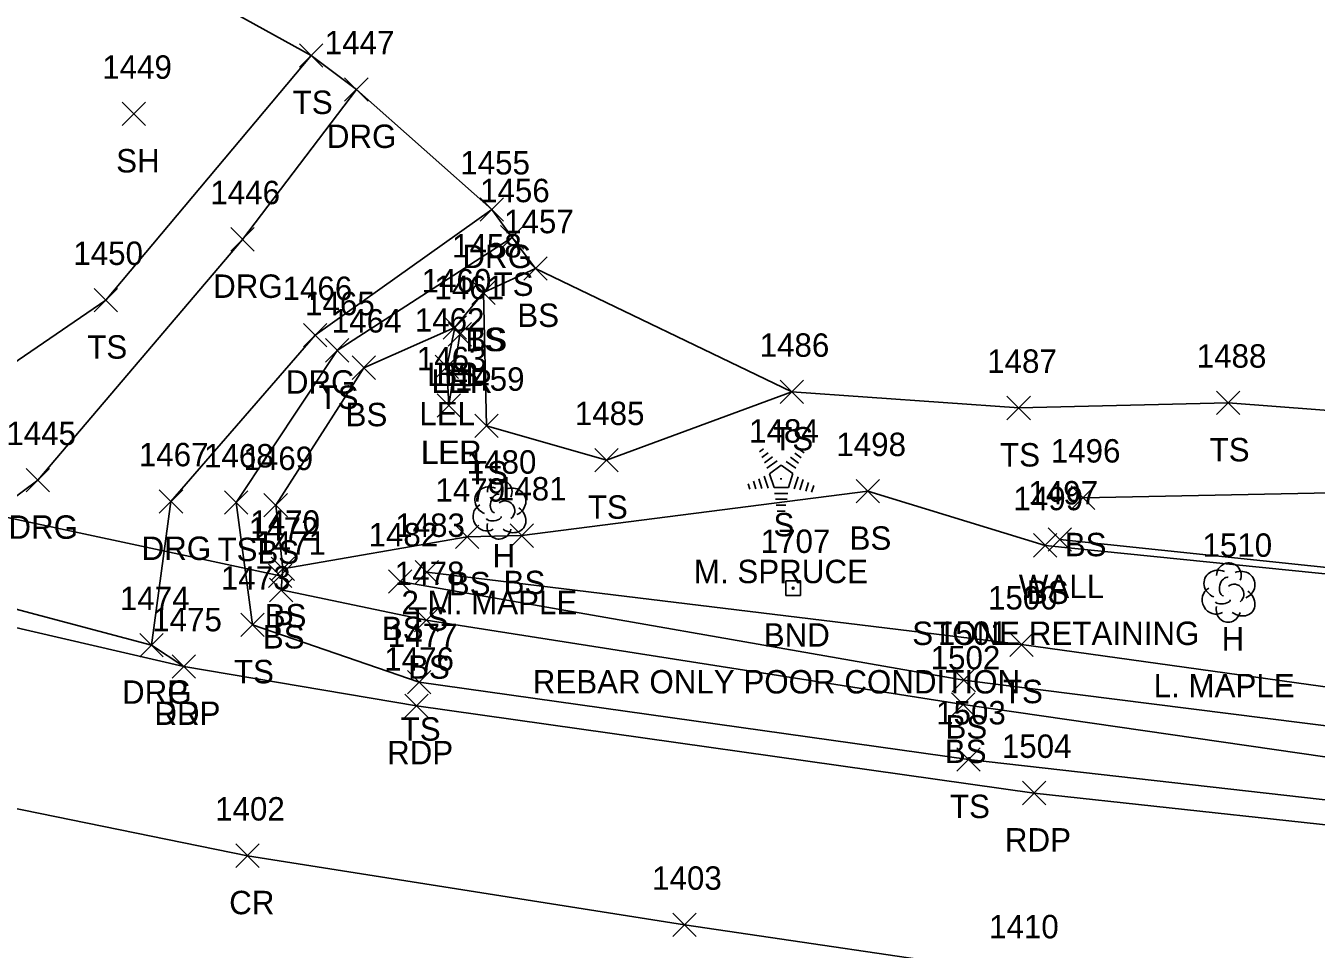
# Model space of a CAD drawing. Extents: x 1547013 to 1549434, y 267998 to 268739.
# Drawn here: x 1548667.4 to 1548777.6, y 268079 to 268157.8 of the extents above; entities that cross this region are included whole.
import ezdxf

# ---------------------------------------------------------------- set-up
doc = ezdxf.new("R2010")
doc.units = 0
for name, color, linetype in [('D_A', 7, 'Continuous'), ('D_I', 7, 'Continuous'), ('D_TIC', 7, 'Continuous'), ('DCP', 7, 'Continuous'), ('L_A', 7, 'Continuous'), ('L_C', 7, 'Continuous'), ('L_I', 7, 'Continuous'), ('L_TIC', 7, 'Continuous'), ('LARO', 7, 'Continuous'), ('LELB', 7, 'Continuous'), ('LSOGP', 7, 'Continuous'), ('LTC', 7, 'Continuous'), ('LTD', 7, 'Continuous'), ('LW', 7, 'Continuous'), ('M_A', 7, 'Continuous'), ('M_C', 7, 'Continuous'), ('M_I', 7, 'Continuous'), ('MHBP', 7, 'Continuous'), ('P_A', 7, 'Continuous'), ('P_I', 7, 'Continuous'), ('P_TIC', 7, 'Continuous'), ('PET', 7, 'Continuous'), ('PRC', 7, 'Continuous'), ('R_A', 7, 'Continuous'), ('R_I', 7, 'Continuous'), ('R_TIC', 7, 'Continuous'), ('RDG', 7, 'Continuous'), ('RDP', 7, 'Continuous')]:
    doc.layers.add(name, color=color, linetype=linetype)

msp = doc.modelspace()

# ---------------------------------------------------------------- linework, layer by layer
at = {"layer": 'D_TIC'}
for points in [[(1548688.17, 268109.86), (1548690.17, 268111.86)], [(1548690.17, 268109.86), (1548688.17, 268111.86)]]:
    msp.add_lwpolyline(points, dxfattribs=at)
at = {"layer": 'DCP'}
msp.add_lwpolyline([(1548636.86, 268122.04), (1548689.17, 268110.86)], dxfattribs=at)
at = {"layer": 'L_TIC'}
for points in [[(1548690.82, 268154.29), (1548692.82, 268156.29)], [(1548692.82, 268154.29), (1548690.82, 268156.29)], [(1548675.67, 268149.3), (1548677.67, 268151.3)], [(1548677.67, 268149.3), (1548675.67, 268151.3)], [(1548707.97, 268138.76), (1548709.97, 268140.76)], [(1548709.97, 268138.76), (1548707.97, 268140.76)], [(1548709.97, 268136.11), (1548711.97, 268138.11)], [(1548711.97, 268136.11), (1548709.97, 268138.11)], [(1548673.28, 268133.4), (1548675.28, 268135.4)], [(1548675.28, 268133.4), (1548673.28, 268135.4)], [(1548705.53, 268134.04), (1548707.53, 268136.04)], [(1548707.53, 268134.04), (1548705.53, 268136.04)], [(1548705.53, 268134.04), (1548707.53, 268136.04)], [(1548707.53, 268134.04), (1548705.53, 268136.04)], [(1548703.07, 268131.06), (1548705.07, 268133.06)], [(1548705.07, 268131.06), (1548703.07, 268133.06)], [(1548703.07, 268131.06), (1548705.07, 268133.06)], [(1548705.07, 268131.06), (1548703.07, 268133.06)], [(1548703.51, 268130.48), (1548705.51, 268132.48)], [(1548705.51, 268130.48), (1548703.51, 268132.48)], [(1548693.03, 268129.11), (1548695.03, 268131.11)], [(1548695.03, 268129.11), (1548693.03, 268131.11)], [(1548702.4, 268127.71), (1548704.4, 268129.71)], [(1548704.4, 268127.71), (1548702.4, 268129.71)], [(1548695.31, 268127.63), (1548697.31, 268129.63)], [(1548697.31, 268127.63), (1548695.31, 268129.63)], [(1548731.85, 268125.56), (1548733.85, 268127.56)], [(1548733.85, 268125.56), (1548731.85, 268127.56)], [(1548702.57, 268124.41), (1548704.57, 268126.41)], [(1548704.57, 268124.41), (1548702.57, 268126.41)], [(1548702.57, 268124.41), (1548704.57, 268126.41)], [(1548704.57, 268124.41), (1548702.57, 268126.41)], [(1548769.11, 268124.63), (1548771.11, 268126.63)], [(1548771.11, 268124.63), (1548769.11, 268126.63)], [(1548751.22, 268124.19), (1548753.22, 268126.19)], [(1548753.22, 268124.19), (1548751.22, 268126.19)], [(1548705.78, 268122.66), (1548707.78, 268124.66)], [(1548707.78, 268122.66), (1548705.78, 268124.66)], [(1548716.02, 268119.73), (1548718.02, 268121.73)], [(1548718.02, 268119.73), (1548716.02, 268121.73)], [(1548738.34, 268117.08), (1548740.34, 268119.08)], [(1548740.34, 268117.08), (1548738.34, 268119.08)], [(1548684.4, 268116.11), (1548686.4, 268118.11)], [(1548686.4, 268116.11), (1548684.4, 268118.11)], [(1548687.78, 268115.89), (1548689.78, 268117.89)], [(1548689.78, 268115.89), (1548687.78, 268117.89)], [(1548756.71, 268116.53), (1548758.71, 268118.53)], [(1548758.71, 268116.53), (1548756.71, 268118.53)], [(1548704.12, 268113.19), (1548706.12, 268115.19)], [(1548706.12, 268113.19), (1548704.12, 268115.19)], [(1548708.8, 268113.29), (1548710.8, 268115.29)], [(1548710.8, 268113.29), (1548708.8, 268115.29)], [(1548708.8, 268113.29), (1548710.8, 268115.29)], [(1548710.8, 268113.29), (1548708.8, 268115.29)], [(1548753.48, 268112.46), (1548755.48, 268114.46)], [(1548755.48, 268112.46), (1548753.48, 268114.46)], [(1548754.74, 268112.95), (1548756.74, 268114.95)], [(1548756.74, 268112.95), (1548754.74, 268114.95)], [(1548688.4, 268110.45), (1548690.4, 268112.45)], [(1548690.4, 268110.45), (1548688.4, 268112.45)], [(1548688.4, 268110.45), (1548690.4, 268112.45)], [(1548690.4, 268110.45), (1548688.4, 268112.45)], [(1548700.68, 268110.18), (1548702.68, 268112.18)], [(1548702.68, 268110.18), (1548700.68, 268112.18)], [(1548698.4, 268109.37), (1548700.4, 268111.37)], [(1548700.4, 268109.37), (1548698.4, 268111.37)], [(1548688.24, 268108.65), (1548690.24, 268110.65)], [(1548690.24, 268108.65), (1548688.24, 268110.65)], [(1548685.8, 268105.68), (1548687.8, 268107.68)], [(1548687.8, 268105.68), (1548685.8, 268107.68)], [(1548700.64, 268106.07), (1548702.64, 268108.07)], [(1548702.64, 268106.07), (1548700.64, 268108.07)], [(1548751.46, 268103.98), (1548753.46, 268105.98)], [(1548753.46, 268103.98), (1548751.46, 268105.98)], [(1548751.46, 268103.98), (1548753.46, 268105.98)], [(1548753.46, 268103.98), (1548751.46, 268105.98)], [(1548700.04, 268100.78), (1548702.04, 268102.78)], [(1548702.04, 268100.78), (1548700.04, 268102.78)], [(1548746.53, 268100.96), (1548748.53, 268102.96)], [(1548748.53, 268100.96), (1548746.53, 268102.96)], [(1548746.47, 268098.87), (1548748.47, 268100.87)], [(1548748.47, 268098.87), (1548746.47, 268100.87)], [(1548746.94, 268094.17), (1548748.94, 268096.17)], [(1548748.94, 268094.17), (1548746.94, 268096.17)]]:
    msp.add_lwpolyline(points, dxfattribs=at)
at = {"layer": 'LARO'}
for points in [[(1548704.07, 268132.06), (1548703.4, 268128.71), (1548703.57, 268125.41)], [(1548704.51, 268131.48), (1548703.57, 268125.41)]]:
    msp.add_lwpolyline(points, dxfattribs=at)
at = {"layer": 'LELB'}
for points in [[(1548691.82, 268155.29), (1548674.28, 268134.4), (1548659.83, 268124.52), (1548649.05, 268118.48), (1548639.38, 268118.89)], [(1548708.97, 268139.76), (1548694.03, 268130.11), (1548685.4, 268117.11), (1548686.8, 268106.68), (1548701.04, 268101.78), (1548747.94, 268095.17), (1548793.98, 268089.97), (1548842.52, 268087.31), (1548868.94, 268086.32)], [(1548710.97, 268137.11), (1548706.53, 268135.04), (1548704.07, 268132.06), (1548696.31, 268128.63), (1548688.78, 268116.89), (1548689.4, 268111.45), (1548689.24, 268109.65), (1548701.64, 268107.07), (1548747.47, 268099.87), (1548796.06, 268092.83), (1548842.33, 268090.57), (1548868.8, 268090.49)], [(1548706.53, 268135.04), (1548706.78, 268123.66), (1548717.02, 268120.73), (1548732.85, 268126.56), (1548752.22, 268125.19), (1548770.11, 268125.63), (1548809.24, 268122.64), (1548831.85, 268121.11), (1548870.82, 268123.01)], [(1548709.8, 268114.29), (1548739.34, 268118.08), (1548754.48, 268113.46), (1548791.6, 268109.68), (1548794.4, 268109.32), (1548819.52, 268109.84), (1548864.97, 268108.07), (1548873.06, 268107.6)], [(1548866.65, 268118.14), (1548838.78, 268114.29), (1548806.27, 268118), (1548784.51, 268118.06), (1548757.71, 268117.53)], [(1548689.4, 268111.45), (1548705.12, 268114.19), (1548709.8, 268114.29)], [(1548701.68, 268111.18), (1548752.46, 268104.98)], [(1548699.4, 268110.37), (1548747.53, 268101.96), (1548796.07, 268095.83), (1548842.07, 268093.87), (1548869.05, 268093.06)], [(1548752.46, 268104.98), (1548796.76, 268098.83), (1548842.79, 268096.87), (1548869.42, 268094.95)]]:
    msp.add_lwpolyline(points, dxfattribs=at)
at = {"layer": 'LSOGP'}
msp.add_lwpolyline([(1548809.24, 268122.64), (1548770.11, 268125.63), (1548752.22, 268125.19), (1548732.85, 268126.56), (1548710.97, 268137.11), (1548708.97, 268139.76), (1548707.23, 268142.13), (1548695.67, 268152.39), (1548691.82, 268155.29), (1548664.24, 268170.51)], dxfattribs=at)
at = {"layer": 'LTC'}
for p, q in [((1548730.09, 268121.44), (1548730.44, 268121.69)), ((1548730.3, 268120.97), (1548730.83, 268121.36)), ((1548730.51, 268120.51), (1548731.21, 268121.02)), ((1548732.74, 268120.98), (1548733.42, 268120.49)), ((1548733.12, 268121.33), (1548733.66, 268120.93)), ((1548733.49, 268121.68), (1548733.91, 268121.37)), ((1548730.72, 268120.04), (1548731.6, 268120.68)), ((1548730.94, 268119.58), (1548731.95, 268120.32)), ((1548731.95, 268120.32), (1548732.95, 268119.59)), ((1548732.37, 268120.63), (1548733.18, 268120.04)), ((1548729.12, 268118.72), (1548729.27, 268118.25)), ((1548729.58, 268118.93), (1548729.79, 268118.28)), ((1548730.03, 268119.15), (1548730.3, 268118.31)), ((1548730.49, 268119.37), (1548730.82, 268118.35)), ((1548730.94, 268119.58), (1548731.33, 268118.39)), ((1548732.95, 268119.59), (1548732.56, 268118.39)), ((1548733.39, 268119.32), (1548733.05, 268118.28)), ((1548733.83, 268119.07), (1548733.54, 268118.19)), ((1548734.28, 268118.82), (1548734.04, 268118.09)), ((1548732.56, 268118.39), (1548731.33, 268118.39)), ((1548732.52, 268117.89), (1548731.38, 268117.89)), ((1548734.72, 268118.57), (1548734.53, 268118)), ((1548732.44, 268117.39), (1548731.45, 268117.39)), ((1548732.35, 268116.89), (1548731.52, 268116.89)), ((1548732.27, 268116.39), (1548731.59, 268116.39))]:
    msp.add_line(p, q, dxfattribs=at)
at = {"layer": 'LTD'}
for p, q in [((1548707.87, 268116.58), (1548707.87, 268116.58)), ((1548707.87, 268116.58), (1548707.87, 268116.58)), ((1548770.12, 268109.48), (1548770.12, 268109.48)), ((1548770.12, 268109.48), (1548770.12, 268109.48))]:
    msp.add_line(p, q, dxfattribs=at)
for centre in [(1548707.91, 268118.02), (1548770.17, 268110.91)]:
    msp.add_arc(centre, 1.05, 335.5272, 180.9563, dxfattribs=at)
for centre, major_axis, ratio, start_param, end_param in [((1548707.08, 268117.25), (1.21, -0.51), 0.895232, 1.570796, 4.712389), ((1548707.66, 268117.04), (-0.208, -0.792), 0.645439, 3.141593, 6.283185), ((1548708.91, 268117.17), (-1.14, -0.48), 0.949671, 1.570796, 4.712389), ((1548706.78, 268115.87), (0.58, -1.04), 0.959034, 3.141593, 6.283185), ((1548708.37, 268116.42), (-0.5, 0.667), 0.989748, 3.141593, 6.283185), ((1548708.87, 268115.75), (-1.09, 0.79), 0.841452, 1.570796, 4.712389), ((1548707.41, 268115.83), (-0.625, -0.083), 0.423636, 0, 3.141593), ((1548707.87, 268115.08), (0.26, 1.06), 0.942809, 1.570796, 4.712389), ((1548769.33, 268110.14), (1.21, -0.51), 0.895232, 1.570796, 4.712389), ((1548771.16, 268110.06), (-1.14, -0.48), 0.949671, 1.570796, 4.712389), ((1548769.91, 268109.93), (-0.208, -0.792), 0.645439, 3.141593, 6.283185), ((1548770.62, 268109.31), (-0.5, 0.667), 0.989748, 3.141593, 6.283185), ((1548769.04, 268108.77), (0.58, -1.04), 0.959034, 3.141593, 6.283185), ((1548769.66, 268108.73), (-0.625, -0.083), 0.423636, 0, 3.141593), ((1548771.12, 268108.64), (-1.09, 0.79), 0.841452, 1.570796, 4.712389), ((1548770.12, 268107.98), (0.26, 1.06), 0.942809, 1.570796, 4.712389)]:
    msp.add_ellipse(centre, major_axis=major_axis, ratio=ratio, start_param=start_param, end_param=end_param, dxfattribs=at)
at = {"layer": 'LW'}
msp.add_lwpolyline([(1548755.74, 268113.95), (1548794.53, 268109.88), (1548819.57, 268110.3), (1548865.06, 268109.14)], dxfattribs=at)
at = {"layer": 'MHBP'}
msp.add_lwpolyline([(1548732.34, 268110.44), (1548733.59, 268110.44), (1548733.59, 268109.19), (1548732.34, 268109.19)], close=True, dxfattribs=at)
msp.add_circle((1548732.96, 268109.81), 0.0833, dxfattribs=at)
at = {"layer": 'P_TIC'}
for points in [[(1548679.93, 268102.12), (1548681.93, 268104.12)], [(1548681.93, 268102.12), (1548679.93, 268104.12)], [(1548699.8, 268098.76), (1548701.8, 268100.76)], [(1548701.8, 268098.76), (1548699.8, 268100.76)], [(1548752.55, 268091.31), (1548754.55, 268093.31)], [(1548754.55, 268091.31), (1548752.55, 268093.31)], [(1548685.38, 268085.96), (1548687.38, 268087.96)], [(1548687.38, 268085.96), (1548685.38, 268087.96)], [(1548722.69, 268080.05), (1548724.69, 268082.05)], [(1548724.69, 268080.05), (1548722.69, 268082.05)]]:
    msp.add_lwpolyline(points, dxfattribs=at)
at = {"layer": 'PET'}
msp.add_lwpolyline([(1548291.29, 268251.79), (1548331.75, 268232.06), (1548365.57, 268215.99), (1548397.04, 268199.92), (1548430.53, 268185.01), (1548469.56, 268167.88), (1548505.57, 268153.53), (1548548.45, 268139.73), (1548572.84, 268130.65), (1548596.65, 268123.57), (1548616.57, 268118.19), (1548655.34, 268109.04), (1548680.93, 268103.12), (1548700.8, 268099.76), (1548753.55, 268092.31), (1548788.11, 268088.53), (1548842.08, 268084.26), (1548868.98, 268083.24)], dxfattribs=at)
at = {"layer": 'PRC'}
msp.add_lwpolyline([(1548285.23, 268237.15), (1548330.43, 268214.75), (1548376.37, 268192.58), (1548426.54, 268169.59), (1548464.29, 268153.5), (1548497.35, 268140.09), (1548534.69, 268126.49), (1548572.93, 268114.69), (1548608.02, 268104.77), (1548637.81, 268097.38), (1548663.07, 268091.69), (1548686.38, 268086.96), (1548723.69, 268081.05), (1548751.9, 268076.9), (1548786.74, 268073.36), (1548818.76, 268070.54), (1548866.8, 268068.08)], dxfattribs=at)
at = {"layer": 'R_TIC'}
for points in [[(1548694.67, 268151.39), (1548696.67, 268153.39)], [(1548696.67, 268151.39), (1548694.67, 268153.39)], [(1548706.23, 268141.13), (1548708.23, 268143.13)], [(1548708.23, 268141.13), (1548706.23, 268143.13)], [(1548684.95, 268138.59), (1548686.95, 268140.59)], [(1548686.95, 268138.59), (1548684.95, 268140.59)], [(1548691.16, 268130.41), (1548693.16, 268132.41)], [(1548693.16, 268130.41), (1548691.16, 268132.41)], [(1548667.48, 268118.02), (1548669.48, 268120.02)], [(1548669.48, 268118.02), (1548667.48, 268120.02)], [(1548678.84, 268116.21), (1548680.84, 268118.21)], [(1548680.84, 268116.21), (1548678.84, 268118.21)], [(1548677.17, 268103.93), (1548679.17, 268105.93)], [(1548679.17, 268103.93), (1548677.17, 268105.93)], [(1548677.17, 268103.93), (1548679.17, 268105.93)], [(1548679.17, 268103.93), (1548677.17, 268105.93)], [(1548679.93, 268102.12), (1548681.93, 268104.12)], [(1548681.93, 268102.12), (1548679.93, 268104.12)]]:
    msp.add_lwpolyline(points, dxfattribs=at)
at = {"layer": 'RDG'}
for points in [[(1548657.06, 268110.53), (1548668.48, 268119.02), (1548685.95, 268139.59), (1548695.67, 268152.39)], [(1548707.23, 268142.13), (1548692.16, 268131.41), (1548679.84, 268117.21), (1548678.17, 268104.93)]]:
    msp.add_lwpolyline(points, dxfattribs=at)
at = {"layer": 'RDP'}
msp.add_lwpolyline([(1548655.34, 268109.04), (1548657.06, 268110.53), (1548678.17, 268104.93), (1548680.93, 268103.12)], dxfattribs=at)

# ---------------------------------------------------------------- texts
at = {"layer": 'D_A'}
msp.add_text('P', height=2, dxfattribs=at).set_placement((1548688.55, 268105.86))
at = {"layer": 'D_I'}
msp.add_text('1472', height=2, dxfattribs=at).set_placement((1548686.48, 268113.86))
at = {"layer": 'L_A'}
for s, p in [('TS', (1548690.23, 268150.29)), ('SH', (1548675.16, 268145.3)), ('TS', (1548707.38, 268134.76)), ('BS', (1548709.41, 268132.11)), ('TS', (1548704.94, 268130.04)), ('BS', (1548704.97, 268130.04)), ('TS', (1548672.69, 268129.4)), ('LEL', (1548701.71, 268127.06)), ('BS', (1548702.51, 268127.06)), ('LER', (1548702.09, 268126.48)), ('TS', (1548692.44, 268125.11)), ('BS', (1548694.75, 268123.63)), ('LEL', (1548701.04, 268123.71)), ('TS', (1548731.26, 268121.56)), ('LER', (1548701.16, 268120.41)), ('LEL', (1548701.21, 268120.41)), ('TS', (1548750.63, 268120.19)), ('TS', (1548768.52, 268120.63)), ('TS', (1548705.19, 268118.66)), ('TS', (1548715.43, 268115.73)), ('S', (1548731.28, 268114.23)), ('BS', (1548737.78, 268113.08)), ('BS', (1548756.15, 268112.53)), ('TS', (1548683.81, 268112.11)), ('BS', (1548687.22, 268111.89)), ('H', (1548707.3, 268111.58)), ('BS', (1548703.56, 268109.19)), ('BS', (1548708.24, 268109.29)), ('BS', (1548708.24, 268109.29)), ('WALL', (1548752.23, 268108.95)), ('BS', (1548752.92, 268108.46)), ('BS', (1548687.84, 268106.45)), ('BS', (1548687.84, 268106.45)), ('TS', (1548700.09, 268106.18)), ('BS', (1548687.68, 268104.65)), ('BS', (1548697.84, 268105.37)), ('H', (1548769.55, 268104.48)), ('TS', (1548685.21, 268101.68)), ('BS', (1548700.08, 268102.07)), ('TS', (1548750.87, 268099.98)), ('TS', (1548750.87, 268099.98)), ('BS', (1548745.97, 268096.96)), ('TS', (1548699.45, 268096.78)), ('BS', (1548745.91, 268094.87)), ('TS', (1548746.35, 268090.17))]:
    msp.add_text(s, height=2, dxfattribs=at).set_placement(p)
at = {"layer": 'L_C'}
for s, p in [('M. SPRUCE', (1548724.49, 268110.23)), ('2 M. MAPLE', (1548699.52, 268107.58)), ('STONE RETAINING', (1548743.13, 268104.95)), ('L. MAPLE', (1548763.74, 268100.48))]:
    msp.add_text(s, height=2, dxfattribs=at).set_placement(p)
at = {"layer": 'L_I'}
for s, p in [('1449', (1548673.97, 268153.3)), ('1456', (1548706.23, 268142.76)), ('1457', (1548708.28, 268140.11)), ('1458', (1548703.84, 268138.04)), ('1458', (1548703.84, 268138.04)), ('1450', (1548671.5, 268137.4)), ('1460', (1548701.24, 268135.06)), ('1460', (1548701.24, 268135.06)), ('1461', (1548702.33, 268134.48)), ('1465', (1548691.29, 268133.11)), ('1464', (1548693.57, 268131.63)), ('1462', (1548700.66, 268131.71)), ('1486', (1548730.1, 268129.56)), ('1463', (1548700.83, 268128.41)), ('1463', (1548700.83, 268128.41)), ('1487', (1548749.53, 268128.19)), ('1488', (1548767.42, 268128.63)), ('1459', (1548704.08, 268126.66)), ('1485', (1548714.32, 268123.73)), ('1484', (1548729.2, 268122.23)), ('1498', (1548736.65, 268121.08)), ('1468', (1548682.66, 268120.11)), ('1496', (1548754.96, 268120.53)), ('1469', (1548686.03, 268119.89)), ('1480', (1548705.09, 268119.58)), ('1479', (1548702.42, 268117.19)), ('1481', (1548707.67, 268117.29)), ('1481', (1548707.67, 268117.29)), ('1497', (1548753.05, 268116.95)), ('1499', (1548751.77, 268116.46)), ('1470', (1548686.62, 268114.45)), ('1470', (1548686.62, 268114.45)), ('1482', (1548696.71, 268113.37)), ('1483', (1548698.99, 268114.18)), ('1471', (1548687.12, 268112.65)), ('1510', (1548767.91, 268112.48)), ('1478', (1548698.95, 268110.07)), ('1473', (1548684.1, 268109.68)), ('1500', (1548749.6, 268107.98)), ('1500', (1548749.6, 268107.98)), ('1477', (1548698.35, 268104.78)), ('1501', (1548745.32, 268104.96)), ('1502', (1548744.7, 268102.87)), ('1503', (1548745.17, 268098.17))]:
    msp.add_text(s, height=2, dxfattribs=at).set_placement(p)
at = {"layer": 'LTC'}
msp.add_text('.', height=1.04, rotation=270, dxfattribs=at).set_placement((1548731.84, 268119.33))
at = {"layer": 'M_A'}
msp.add_text('BND', height=2, dxfattribs=at).set_placement((1548730.45, 268104.81))
at = {"layer": 'M_C'}
msp.add_text('REBAR ONLY POOR CONDITION', height=2, dxfattribs=at).set_placement((1548710.73, 268100.81))
at = {"layer": 'M_I'}
msp.add_text('1707', height=2, dxfattribs=at).set_placement((1548730.19, 268112.81))
at = {"layer": 'P_A'}
for s, p in [('RDP', (1548678.42, 268098.12)), ('RDP', (1548698.29, 268094.76)), ('RDP', (1548751.04, 268087.31)), ('CR', (1548684.81, 268081.96))]:
    msp.add_text(s, height=2, dxfattribs=at).set_placement(p)
at = {"layer": 'P_I'}
for s, p in [('1475', (1548678.24, 268106.12)), ('1476', (1548698.05, 268102.76)), ('1504', (1548750.78, 268095.31)), ('1402', (1548683.61, 268089.96)), ('1403', (1548720.92, 268084.05)), ('1410', (1548749.69, 268079.9))]:
    msp.add_text(s, height=2, dxfattribs=at).set_placement(p)
at = {"layer": 'R_A'}
for s, p in [('DRG', (1548693.15, 268147.39)), ('DRG', (1548704.72, 268137.13)), ('DRG', (1548683.44, 268134.59)), ('DRG', (1548689.65, 268126.41)), ('DRG', (1548665.96, 268114.02)), ('DRG', (1548677.33, 268112.21)), ('DRG', (1548675.66, 268099.93)), ('DRP', (1548675.66, 268099.93)), ('DRP', (1548678.42, 268098.12))]:
    msp.add_text(s, height=2, dxfattribs=at).set_placement(p)
at = {"layer": 'R_I'}
for s, p in [('1447', (1548692.97, 268155.39)), ('1455', (1548704.54, 268145.13)), ('1446', (1548683.2, 268142.59)), ('1466', (1548689.37, 268134.41)), ('1445', (1548665.78, 268122.02)), ('1467', (1548677.1, 268120.21)), ('1474', (1548675.48, 268107.93)), ('1474', (1548675.48, 268107.93)), ('1475', (1548678.24, 268106.12))]:
    msp.add_text(s, height=2, dxfattribs=at).set_placement(p)

doc.saveas('drawing.dxf')
